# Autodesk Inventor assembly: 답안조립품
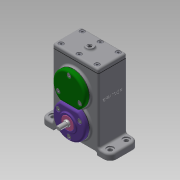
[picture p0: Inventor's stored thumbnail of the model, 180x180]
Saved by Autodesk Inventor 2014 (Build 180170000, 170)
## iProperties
Created: 2020-05
Part Number: 답안조립품
Document SubType Name: Assembly
Designer: kh
Mass: 1078.8 g
Surface Area: 1578.54 cm^2
Volume: 384.341 cm^3
Density: 2.80688 g/cm^3
Author: kh
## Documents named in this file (24)
- C:\Users\kh\Desktop\이주현-600506V1035\답안조립품.iam
- C:\Users\kh\Desktop\이주현-600506V1035\본체.ipt
- C:\Users\kh\Desktop\이주현-600506V1035\개스킷 A.ipt
- C:\Users\kh\Desktop\이주현-600506V1035\개스킷 B.ipt
- C:\Users\kh\Desktop\이주현-600506V1035\개스킷 C.ipt
- C:\Users\kh\Desktop\이주현-600506V1035\베어링 6001.ipt
- 베어링 6001.ipt
- C:\Users\kh\Desktop\이주현-600506V1035\베어링 6002.ipt
- 베어링 6002.ipt
- C:\Users\kh\Desktop\이주현-600506V1035\볼트 M4.ipt
- C:\Users\kh\Desktop\이주현-600506V1035\스퍼기어 A.ipt
- C:\Users\kh\Desktop\이주현-600506V1035\스퍼기어 B.ipt
- C:\Users\kh\Desktop\이주현-600506V1035\오일 실 10 20 7.ipt
- C:\Users\kh\Desktop\이주현-600506V1035\오일 실 12 22 7.ipt
- C:\Users\kh\Desktop\이주현-600506V1035\축 A.ipt
- C:\Users\kh\Desktop\이주현-600506V1035\축 B.ipt
- C:\Users\kh\Desktop\이주현-600506V1035\칼라.ipt
- C:\Users\kh\Desktop\이주현-600506V1035\커버 A.ipt
- C:\Users\kh\Desktop\이주현-600506V1035\커버 B.ipt
- C:\Users\kh\Desktop\이주현-600506V1035\커버 C.ipt
- C:\Users\kh\Desktop\이주현-600506V1035\커버 D.ipt
- C:\Users\kh\Desktop\이주현-600506V1035\커버 E.ipt
- C:\Users\kh\Desktop\이주현-600506V1035\키 4 x 4 x 12.ipt
- C:\Users\kh\Desktop\이주현-600506V1035\키 5 x 5 x 12.ipt
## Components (5 placed, 3 different names)
1. 개스킷 C:1
2. 개스킷 B:1
3. 개스킷 B:2
4. 개스킷 B:3
5. 개스킷 A:1
